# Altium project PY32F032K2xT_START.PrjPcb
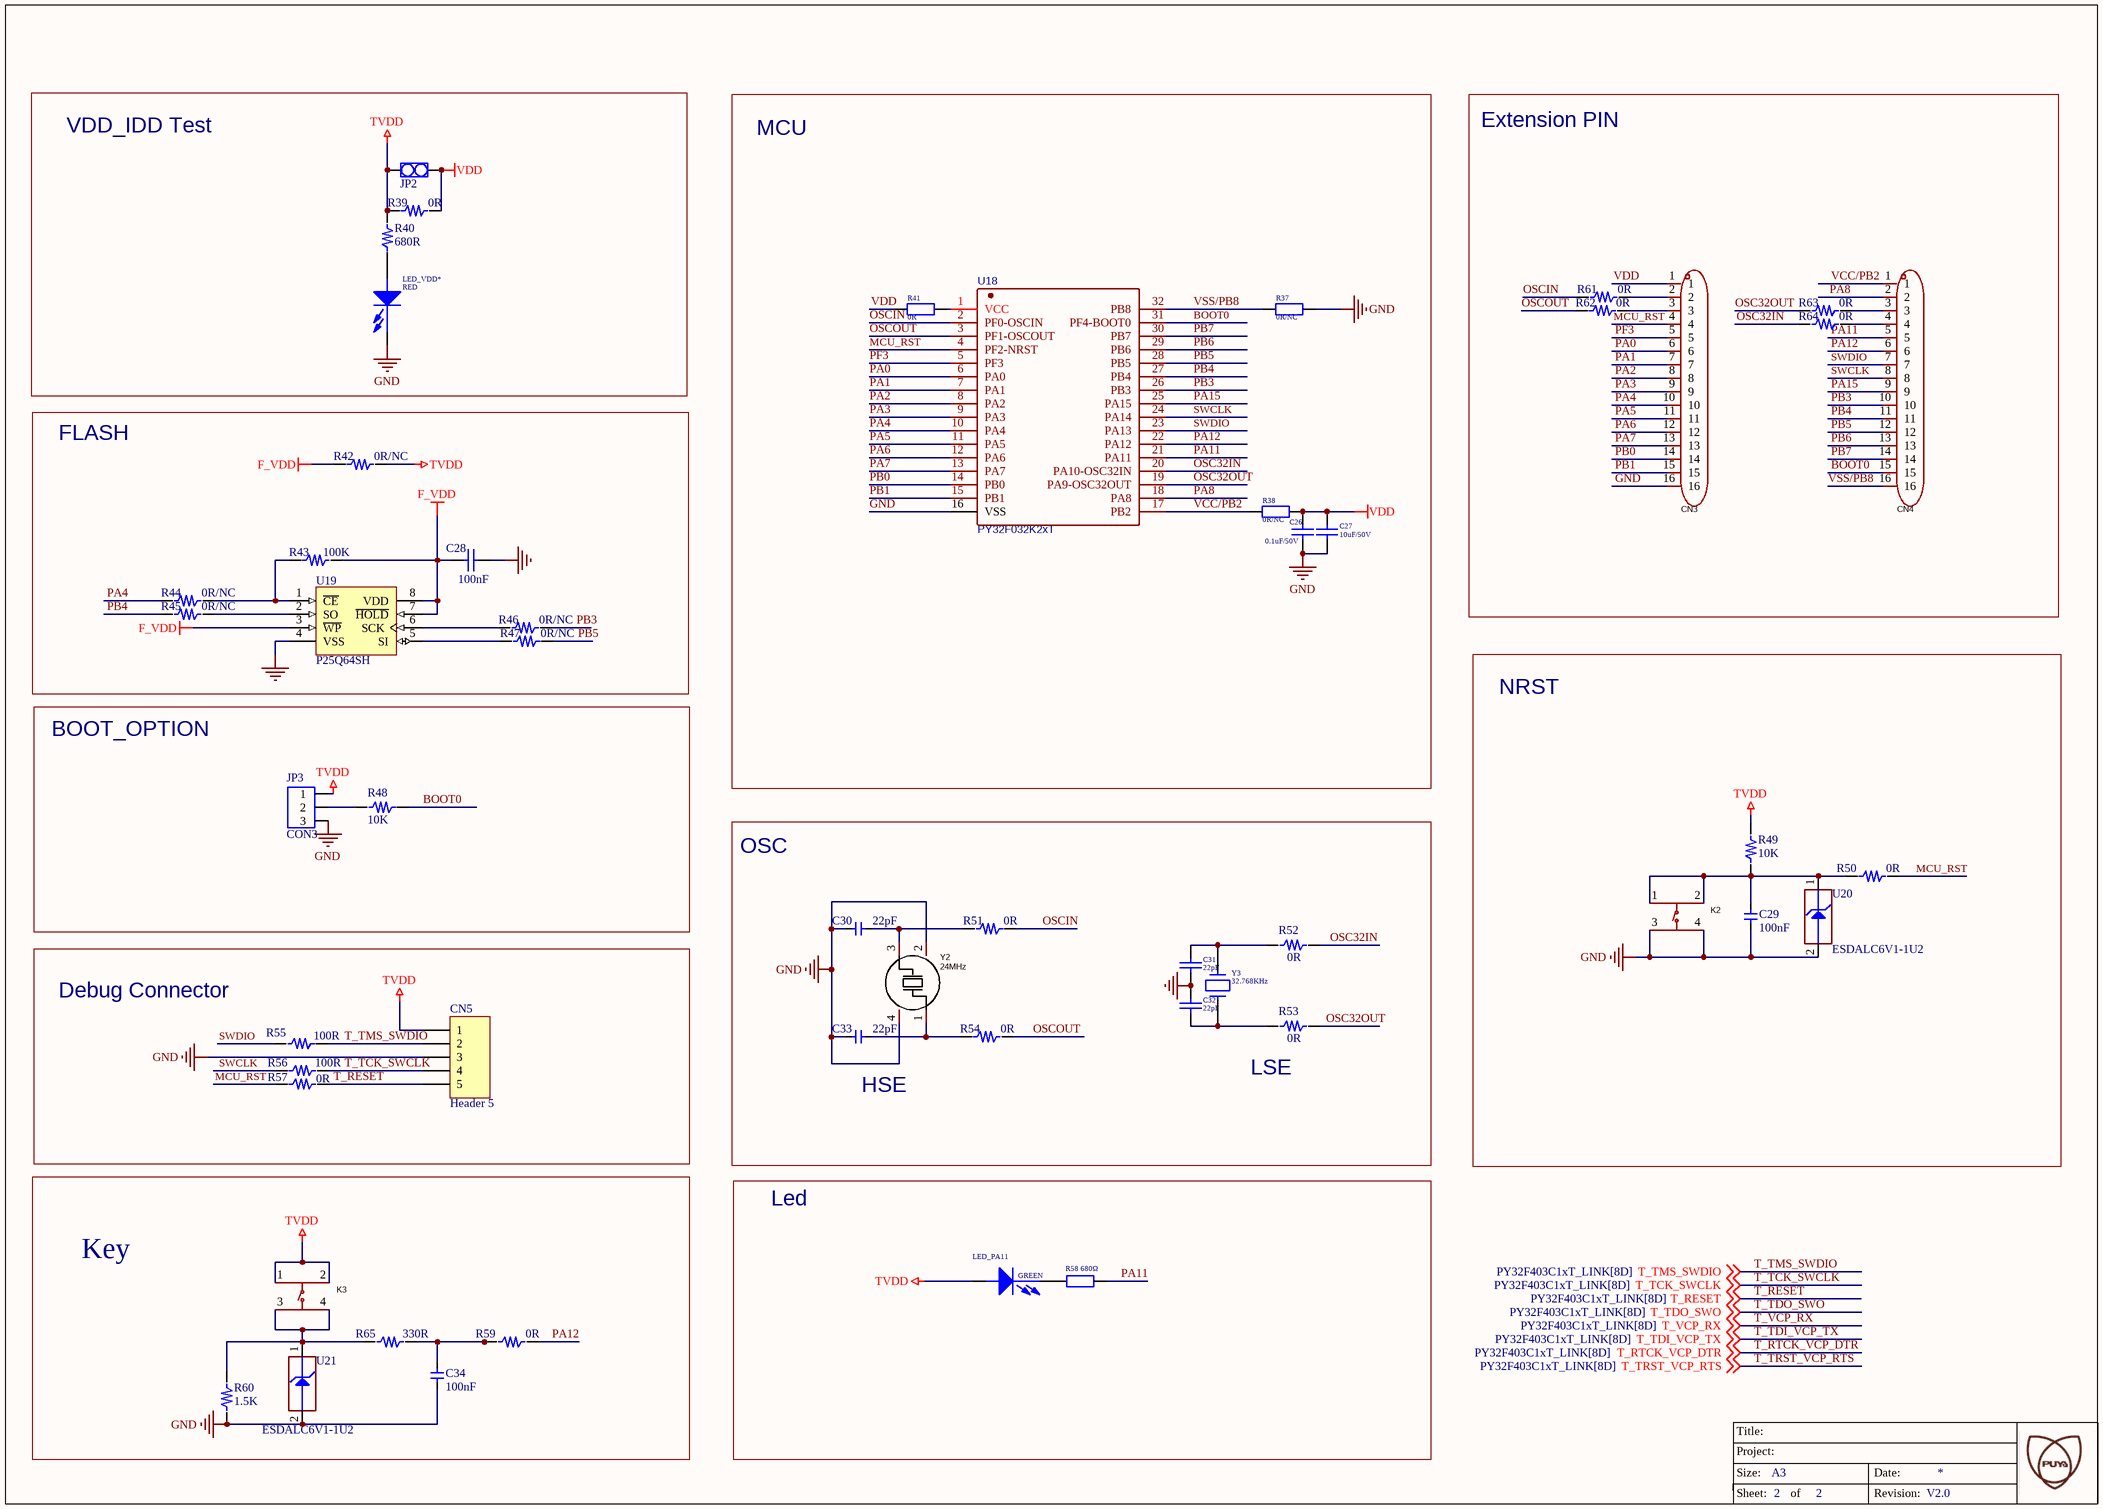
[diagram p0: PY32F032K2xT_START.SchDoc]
2 sheets, 141 parts. Net scope: global (net labels, ports and power ports of the same name join across sheets).
Board file: PY32F032K2xT_START.PcbDoc
Sheets:
  PY32F032K2xT_START.SchDoc
  PY32F403C1xT_LINK.SchDoc

## Sheet PY32F032K2xT_START.SchDoc: =DocumentName
size A3; Revision: V2.0; SheetNumber: 2; SheetTotal: 2; Project: PY32F032K2xT_START.PrjPcb

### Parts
C26  0.1uF/50V  [0603C]
C27  10uF/50V  [0603C]
C28  100nF  [C0603]
C29  100nF  [C0603]
C30  22pF  [C0603]
C31  22pF  [0603C]
C32  22pF  [0603C]
C33  22pF  [C0603]
C34  100nF  [C0603]
CN3  X6511WV-18H-C60D30  [CON 1X16P]  (value not drawn)
CN4  X6511WV-18H-C60D30  [CON 1X16P]  (value not drawn)
CN5  Header 5  [HDR1X5]
JP2  CON2  [CON2]  (value not drawn)
JP3  CON3  [CON3]
K2  TS-KG02S  [SWITCH]  (value not drawn)
K3  TS-KG02S  [SWITCH]  (value not drawn)
LED_PA11  GREEN  [0603_LED]
LED_VDD*  RED  [0603_LED]
R37  0R/NC  [R0603]
R38  0R/NC  [R0603]
R39  0R  [JP2_SMD]
R40  680R  [R0603]
R41  0R  [R0603]
R42  0R/NC  [JP2_SMD]
R43  100K  [R0603]
R44  0R/NC  [JP2_SMD]
R45  0R/NC  [JP2_SMD]
R46  0R/NC  [JP2_SMD]
R47  0R/NC  [JP2_SMD]
R48  10K  [R0603]
R49  10K  [R0603]
R50  0R  [JP2_SMD]
R51  0R  [JP2_SMD]
R52  0R  [JP2_SMD]
R53  0R  [JP2_SMD]
R54  0R  [JP2_SMD]
R55  100R  [R0603]
R56  100R  [R0603]
R57  0R  [JP2_SMD]
R58  680Ω  [R0603]
R59  0R  [JP2_SMD]
R60  1.5K  [R0603]
R61  0R  [JP2_SMD]
R62  0R  [JP2_SMD]
R63  0R  [JP2_SMD]
R64  0R  [JP2_SMD]
R65  330R  [R0603]
U18  PY32F032K2xT  [LQFP-32_L7.0-W7.0-P0.80-LS9.0-BL]
U19  P25Q64SH  [SOP-8P]
U20  value ESDALC6V1-1U2  [ESD_ST0201]  (hidden comment: ESD-TRANSIL)
U21  value ESDALC6V1-1U2  [ESD_ST0201]  (hidden comment: ESD-TRANSIL)
Y2  24MHz  [CRYSTAL-SMD_4P-L3.2-W2.5-BL]
Y3  32.768KHz  [CRYSTAL-SMD_L3.2-W1.5-1]

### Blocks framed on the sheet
VDD_IDD Test: JP2 LED_VDD* R39 R40
MCU: C26 C27 R37 R38 R41 U18
Extension PIN: CN3 CN4 R61-R64
FLASH: C28 R42-R47 U19
NRST: C29 K2 R49 R50 U20
BOOT_OPTION: JP3 R48
Debug Connector: CN5 R55-R57
Key: C34 K3 R59 R60 R65 U21
Led: LED_PA11 R58

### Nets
F_VDD: C28.2 R42.1 R43.2 U19.3(~{WP}) U19.7(~{HOLD}) U19.8(VDD)
GND: C26.1 C27.1 C28.1 C29.1 C30.1 C31.2 C32.1 C33.1 C34.1 CN3.16 CN5.3 JP3.3 K2.3 K2.4 LED_VDD*.2(CATHODE) R37.2 R60.1 U18.16(VSS) U19.4(VSS) U20.2(GND) U21.2(GND) Y2.2(GND) Y2.4(GND)
TVDD: CN5.1 JP2.1 JP3.1 K3.1 K3.2 LED_PA11.1(ANODE) R39.1 R40.2 R42.2 R49.1
VDD: C26.2 C27.2 CN3.1 JP2.2 R38.2 R39.2 R41.1
BOOT0: CN4.15 R48.2 U18.31(PF4-BOOT0)
MCU_RST: CN3.4 R50.2 R57.2 U18.4(PF2-NRST)
OSC32IN: R52.1 R64.1 U18.20(PA10-OSC32IN)
OSC32OUT: R53.1 R63.1 U18.19(PA9-OSC32OUT)
OSCIN: R51.2 R61.1 U18.2(PF0-OSCIN)
OSCOUT: R54.2 R62.1 U18.3(PF1-OSCOUT)
PA0: CN3.6 U18.6(PA0)
PA1: CN3.7 U18.7(PA1)
PA2: CN3.8 U18.8(PA2)
PA3: CN3.9 U18.9(PA3)
PA4: CN3.10 R44.1 U18.10(PA4)
PA5: CN3.11 U18.11(PA5)
PA6: CN3.12 U18.12(PA6)
PA7: CN3.13 U18.13(PA7)
PA8: CN4.2 U18.18(PA8)
PA11: CN4.5 R58.2 U18.21(PA11)
PA12: CN4.6 R59.2 U18.22(PA12)
PA15: CN4.9 U18.25(PA15)
PB0: CN3.14 U18.14(PB0)
PB1: CN3.15 U18.15(PB1)
PB3: CN4.10 R46.2 U18.26(PB3)
PB4: CN4.11 R45.1 U18.27(PB4)
PB5: CN4.12 R47.2 U18.28(PB5)
PB6: CN4.13 U18.29(PB6)
PB7: CN4.14 U18.30(PB7)
PF3: CN3.5 U18.5(PF3)
SWCLK: CN4.8 R56.2 U18.24(PA14)
SWDIO: CN4.7 R55.2 U18.23(PA13)
T_RESET: CN5.5 R57.1 ; off-sheet T_RESET
T_TCK_SWCLK: CN5.4 R56.1 ; off-sheet T_TCK_SWCLK
T_TMS_SWDIO: CN5.2 R55.1 ; off-sheet T_TMS_SWDIO
VCC/PB2: CN4.1 R38.1 U18.17(PB2)
VSS/PB8: CN4.16 R37.1 U18.32(PB8)
NetC29_2: C29.2 K2.1 K2.2 R49.2 R50.1 U20.1(IO1)
NetC30_2: C30.2 R51.1 Y2.3(OSC2)
NetC31_1: C31.1 R52.2 Y3.2
NetC32_2: C32.2 R53.2 Y3.1
NetC33_2: C33.2 R54.1 Y2.1(OSC1)
NetC34_2: C34.2 R59.1 R65.1
NetCN3_2: CN3.2 R61.2
NetCN3_3: CN3.3 R62.2
NetCN4_3: CN4.3 R63.2
NetCN4_4: CN4.4 R64.2
NetJP3_2: JP3.2 R48.1
NetK3_3: K3.3 K3.4 R60.2 R65.2 U21.1(IO1)
NetLED_PA11_2: LED_PA11.2(CATHODE) R58.1
NetLED_VDD*_1: LED_VDD*.1(ANODE) R40.1
NetR41_2: R41.2 U18.1(VCC)
NetR43_1: R43.1 R44.2 U19.1(~{CE})
NetR45_2: R45.2 U19.2(SO)
NetR46_1: R46.1 U19.6(SCK)
NetR47_1: R47.1 U19.5(SI)

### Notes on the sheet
- OSC
- (near C33) HSE
- (near R53) LSE

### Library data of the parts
C26 C27 = CAP: Capacitor; Value: 2.2uF
C28 = 贴片高压陶瓷电容: Capacitor (Semiconductor SIM Model); 器件封装(外观): 0603; Value: 104
C29 C30 C33 C34 = C0603: PCB DECAL: 0603
C31 C32 = Cap: Capacitor
CN3 CN4 = CON 1X16P: Manufacturer: XKB Connection(中国星坤); Symbol: X6511WV-18H-C30D60; Add into BOM: yes; Pin Structure: 1x18P; Pitch: 2.54mm; Circluar Pins/Square Pins: 方针; Current Rating (Max): 3A; Voltage Rating (Max): 250V; Soldering Temperature(Max): 260℃
CN5 = Header 5: Header, 5-Pin
JP2 = CON2_DIP
K2 K3 = TS-KG02S-AT50F: Manufacturer: HANBO(汉博); Add into BOM: yes; Circuit: 单刀单掷; Actuator Style: 圆形按钮; Operating Force: 250gf; Switch Length: 6mm; Switch Height: 5mm; Strike Gundam: 不带; Contact Current: 50mA; Voltage Rating (DC): 12V; Insulation Resistance: 100MΩ; Actuator/Cap Color: 黑色; Pin Style: 鸥翼型
LED_PA11 LED_VDD* = PDI-E803_Dup1
R37 R38 R41 R58 = Res: Resistor; 器件封装(外观): 0603; Value: 10K
R39 R40 R42-R57 R59-R65 = R0603: PCB DECAL: 0603
U18 = PY32F032K2xT: LQFP32(7*7); BOM_Manufacturer: PUYA(普冉)
U19 = SST25VF010: Value: SST25VF020B; 器件封装(外观): SOP8
U20 U21 = ESD-TRANSIL: ESD protection 6V1; Internal_Part_Number: MCD-00170; Part_Type: Diode; Manufacturer: STMICROELECTRONICS; ECCN_US: EAR99; ECCN_EU: NEC; Provided_By: Subcon; Initial_Board_Reference: MB1274
Y2 = ABM8AIG-24.000MHZ-82Z-T: ±20ppm , 12.5pF , T_use: -40°C~125°C; Manufacturer: ABRACON; Add into BOM: yes; External load capacitor: 8pF; Frequency Stability(Full temperature range): ±50ppm; Equivalent Series Resistance (ESR): 50Ω
Y3 = CRYSTAL_1: Crystal; Value: X503225MSB2GI

## Sheet PY32F403C1xT_LINK.SchDoc: =DocumentName
size A3; Revision: V2.0; SheetNumber: 1; SheetTotal: 2; Project: PY32F032K2xT_START.PrjPcb
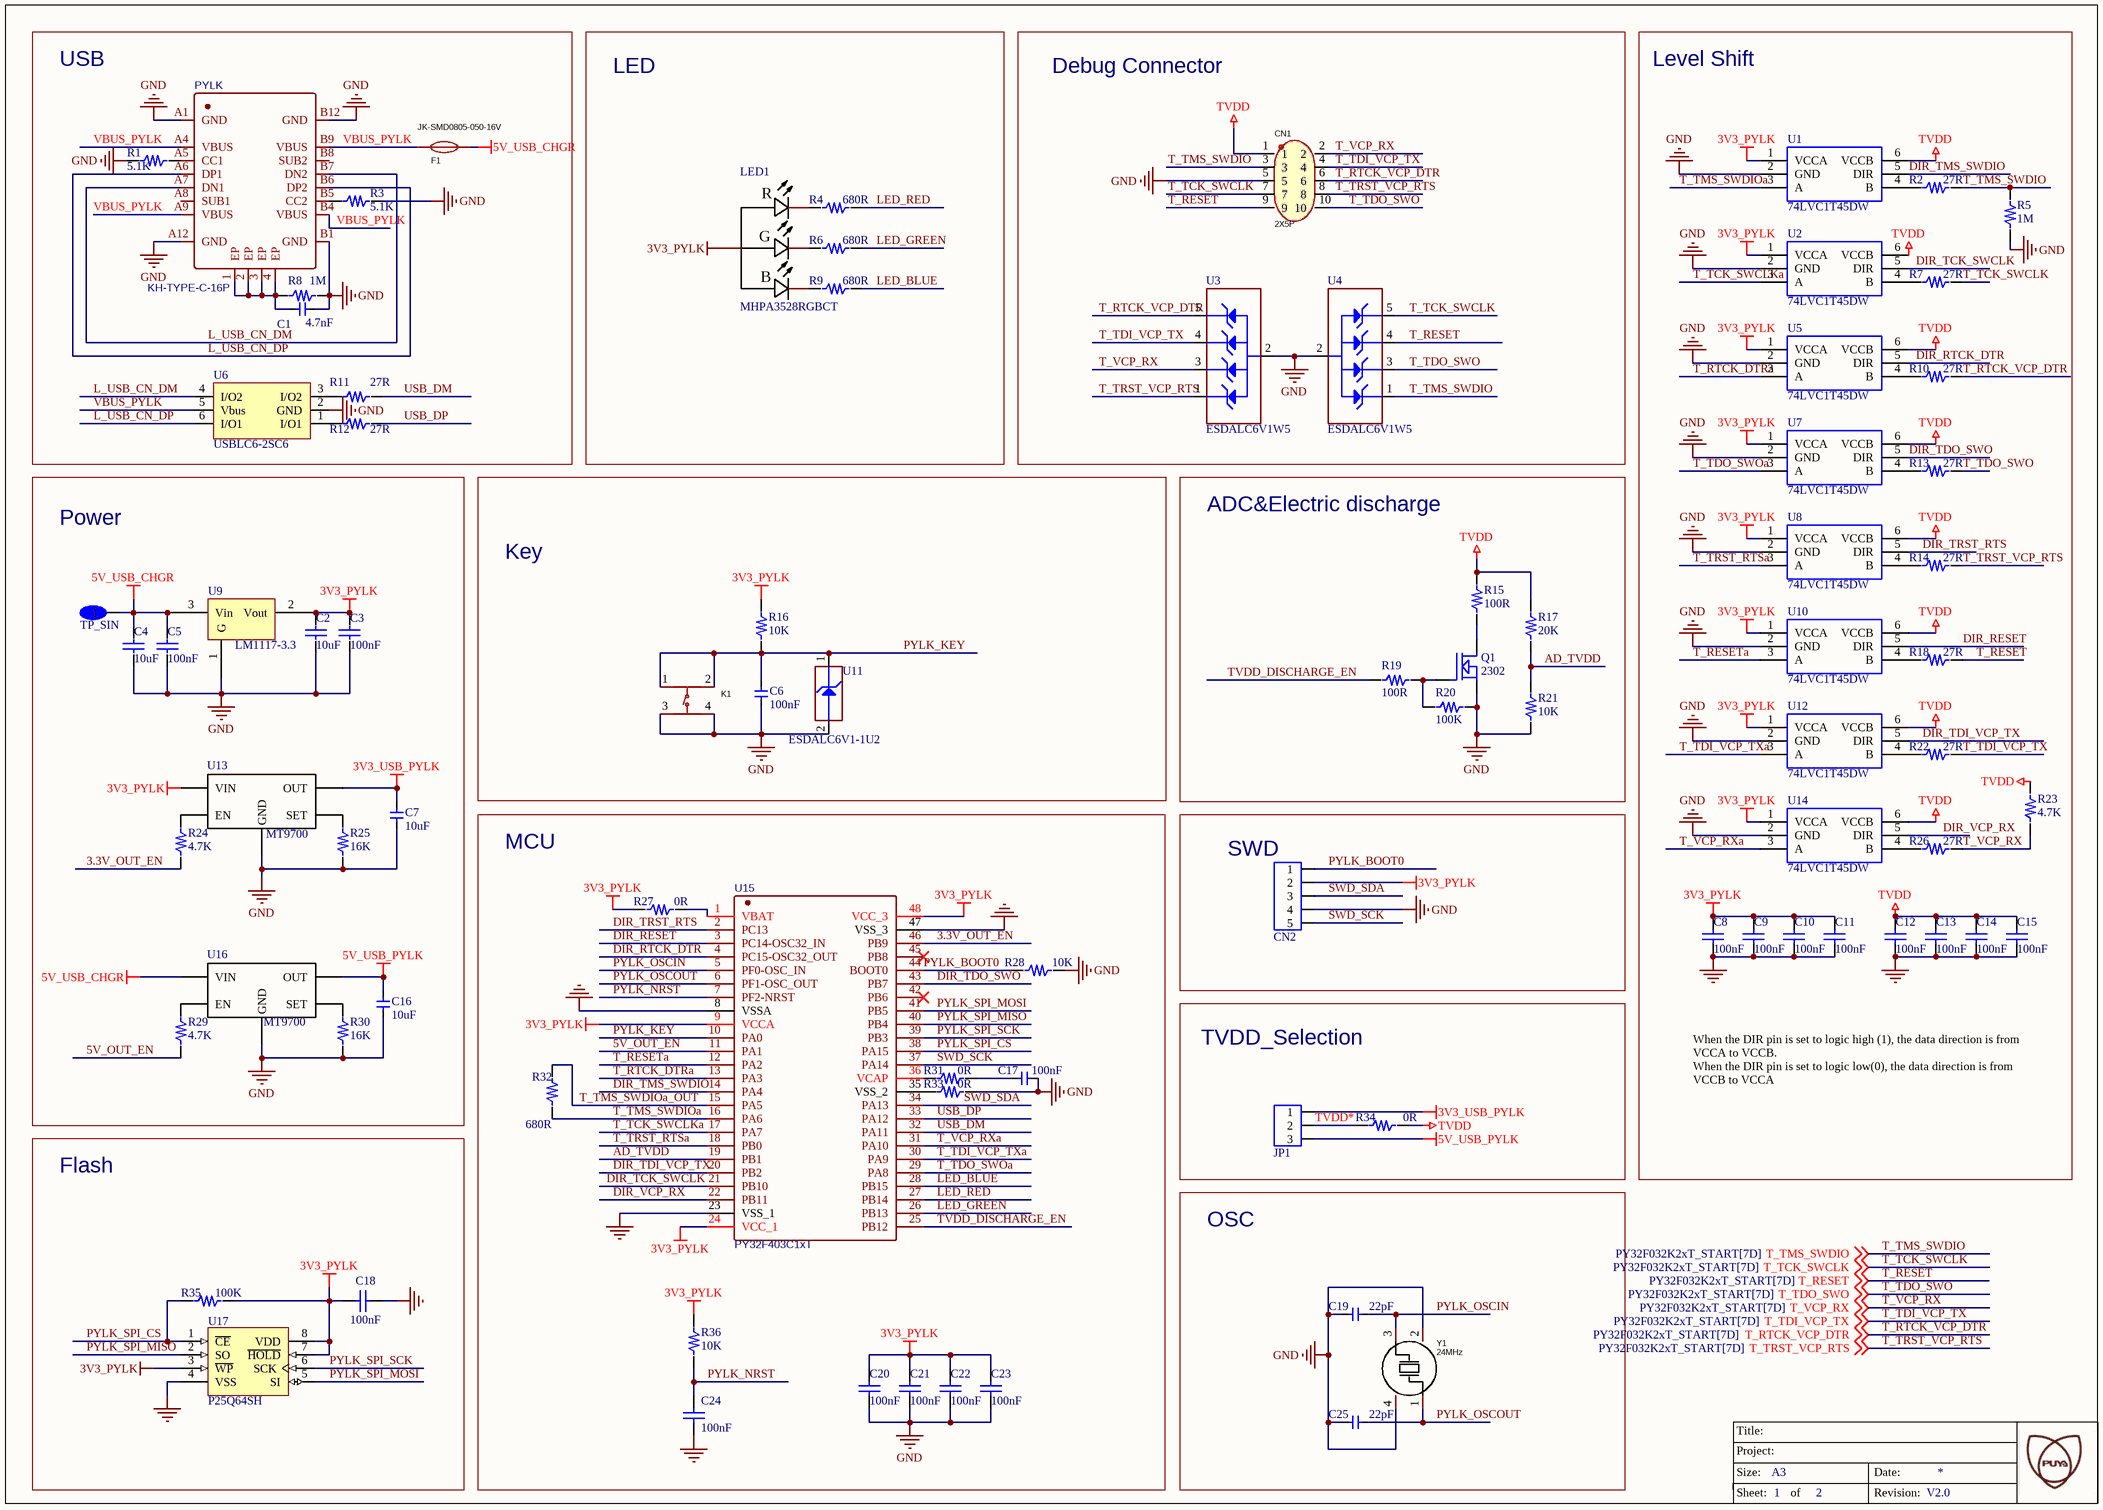
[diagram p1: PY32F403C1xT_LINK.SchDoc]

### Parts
5V_USB_CHGR  TP_SIN  [TP_SIN]
C1  4.7nF  [C0603]
C2  10uF  [C0805]
C3  100nF  [C0603]
C4  10uF  [C0805]
C5  100nF  [C0603]
C6  100nF  [C0603]
C7  10uF  [C0805]
C8  100nF  [C0603]
C9  100nF  [C0603]
C10  100nF  [C0603]
C11  100nF  [C0603]
C12  100nF  [C0603]
C13  100nF  [C0603]
C14  100nF  [C0603]
C15  100nF  [C0603]
C16  10uF  [C0805]
C17  100nF  [C0603]
C18  100nF  [C0603]
C19  22pF  [C0603]
C20  100nF  [C0603]
C21  100nF  [C0603]
C22  100nF  [C0603]
C23  100nF  [C0603]
C24  100nF  [C0603]
C25  22pF  [C0603]
CN1  2X5P  [HDR2X5]
CN2  CON5  [CON5]  (value not drawn)
F1  JK-SMD0805-050-16V  [F0805]
JP1  CON3  [CON3]  (value not drawn)
K1  TS-KG02S  [SWITCH]  (value not drawn)
LED1  MHPA3528RGBCT  [LED-ARRAY-SMD_4P-L3.5-W2.8-TL]
PYLK  KH-TYPE-C-16P  [USB-C-SMD_KH-TYPE-C-16P]
Q1  2302  [SOT23]
R1  5.1K  [R0603]
R2  27R  [R0603]
R3  5.1K  [R0603]
R4  680R  [R0603]
R5  1M  [R0603]
R6  680R  [R0603]
R7  27R  [R0603]
R8  1M  [R0603]
R9  680R  [R0603]
R10  27R  [R0603]
R11  27R  [R0603]
R12  27R  [R0603]
R13  27R  [R0603]
R14  27R  [R0603]
R15  100R  [R0805]
R16  10K  [R0603]
R17  20K  [R0603]
R18  27R  [R0603]
R19  100R  [R0603]
R20  100K  [R0603]
R21  10K  [R0603]
R22  27R  [R0603]
R23  4.7K  [R0603]
R24  4.7K  [R0603]
R25  16K  [R0603]
R26  27R  [R0603]
R27  0R  [JP2_SMD]
R28  10K  [R0603]
R29  4.7K  [R0603]
R30  16K  [R0603]
R31  0R  [JP2_SMD]
R32  680R  [R0603]
R33  0R  [JP2_SMD]
R34  0R  [JP2_SMD]
R35  100K  [R0603]
R36  10K  [R0603]
U1  74LVC1T45DW  [SOT363]
U2  74LVC1T45DW  [SOT363]
U3  value ESDALC6V1W5  [ESD_SOT323-5L]  (hidden comment: ESD_6V1)
U4  value ESDALC6V1W5  [ESD_SOT323-5L]  (hidden comment: ESD_6V1)
U5  74LVC1T45DW  [SOT363]
U6  USBLC6-2SC6  [SOT23-6]
U7  74LVC1T45DW  [SOT363]
U8  74LVC1T45DW  [SOT363]
U9  LM1117-3.3  [LM1117-3.3]
U10  74LVC1T45DW  [SOT363]
U11  value ESDALC6V1-1U2  [ESD_ST0201]  (hidden comment: ESD-TRANSIL)
U12  74LVC1T45DW  [SOT363]
U13  MT9700  [SOT23-5]
U14  74LVC1T45DW  [SOT363]
U15  PY32F403C1xT  [LQFP-48_L7.0-W7.0-P0.50-LS9.0-BL]
U16  MT9700  [SOT23-5]
U17  P25Q64SH  [SOP-8P]
Y1  24MHz  [CRYSTAL-SMD_4P-L3.2-W2.5-BL]

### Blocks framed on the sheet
USB: C1 F1 PYLK R1 R3 R8 R11 R12 U6
LED: LED1 R4 R6 R9
Debug Connector: CN1 U3 U4
Level Shift: C8-C15 R2 R5 R7 R10 R13 R14 R18 R22 R23 R26 U1 U2 U5 U7 U8 U10 U12 U14
Power: 5V_USB_CHGR C2-C5 C7 C16 R24 R25 R29 R30 U9 U13 U16
Key: C6 K1 R16 U11
ADC&Electric discharge: Q1 R15 R17 R19-R21
MCU: C17 C20-C24 R27 R28 R31-R33 R36 U15
SWD: CN2
TVDD_Selection: JP1 R34
Flash: C18 R35 U17
OSC: C19 C25 Y1

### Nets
3V3_PYLK: C2.2 C3.2 C8.2 C9.2 C10.2 C11.2 C18.2 C20.2 C21.2 C22.2 C23.2 CN2.2 LED1.1(-) R16.2 R27.1 R35.2 R36.2 U1.1(VCCA) U2.1(VCCA) U5.1(VCCA) U7.1(VCCA) U8.1(VCCA) U9.2(Vout) U10.1(VCCA) U12.1(VCCA) U13.5(VIN) U14.1(VCCA) U15.9(VCCA) U15.24(VCC_1) U15.48(VCC_3) U17.3(~{WP}) U17.7(~{HOLD}) U17.8(VDD)
3V3_USB_PYLK: C7.2 JP1.1 U13.1(OUT)
5V_USB_CHGR: 5V_USB_CHGR.1 C4.2 C5.2 F1.2 U9.3(Vin) U16.5(VIN)
5V_USB_PYLK: C16.2 JP1.3 U16.1(OUT)
GND: C1.1 C2.1 C3.1 C4.1 C5.1 C6.1 C7.1 C8.1 C9.1 C10.1 C11.1 C12.1 C13.1 C14.1 C15.1 C16.1 C17.1 C18.1 C19.1 C20.1 C21.1 C22.1 C23.1 C24.1 C25.1 CN1.5 CN2.4 K1.3 K1.4 PYLK.A1(GND) PYLK.A12(GND) PYLK.B1(GND) PYLK.B12(GND) Q1.2(S) R1.1 R3.2 R5.1 R8.2 R20.1 R21.1 R25.1 R28.2 R30.1 R33.2 U1.2(GND) U2.2(GND) U3.2(GND) U4.2(GND) U5.2(GND) U6.2(GND) U7.2(GND) U8.2(GND) U9.1(G) U10.2(GND) U11.2(GND) U12.2(GND) U13.2(GND) U14.2(GND) U15.8(VSSA) U15.23(VSS_1) U15.47(VSS_3) U16.2(GND) U17.4(VSS) Y1.2(GND) Y1.4(GND)
TVDD: C12.2 C13.2 C14.2 C15.2 CN1.1 R15.2 R17.2 R23.2 R34.2 U1.6(VCCB) U2.6(VCCB) U5.6(VCCB) U7.6(VCCB) U8.6(VCCB) U10.6(VCCB) U12.6(VCCB) U14.6(VCCB)
3.3V_OUT_EN: R24.1 U15.46(PB9)
5V_OUT_EN: R29.1 U15.11(PA1)
AD_TVDD: R17.1 R21.2 U15.19(PB1)
DIR_RESET: U10.5(DIR) U15.3(PC14-OSC32_IN)
DIR_RTCK_DTR: U5.5(DIR) U15.4(PC15-OSC32_OUT)
DIR_TCK_SWCLK: U2.5(DIR) U15.21(PB10)
DIR_TDI_VCP_TX: U12.5(DIR) U15.20(PB2)
DIR_TDO_SWO: U7.5(DIR) U15.43(PB7)
DIR_TMS_SWDIO: U1.5(DIR) U15.14(PA4)
DIR_TRST_RTS: U8.5(DIR) U15.2(PC13)
DIR_VCP_RX: U14.5(DIR) U15.22(PB11)
L_USB_CN_DM: PYLK.A7(DN1) PYLK.B7(DN2) U6.4(I/O2)
L_USB_CN_DP: PYLK.A6(DP1) PYLK.B6(DP2) U6.6(I/O1)
LED_BLUE: R9.2 U15.28(PB15)
LED_GREEN: R6.2 U15.26(PB13)
LED_RED: R4.2 U15.27(PB14)
PYLK_BOOT0: CN2.1 R28.1 U15.44(BOOT0)
PYLK_KEY: C6.2 K1.1 K1.2 R16.1 U11.1(IO1) U15.10(PA0)
PYLK_NRST: C24.2 R36.1 U15.7(PF2-NRST)
PYLK_OSCIN: C19.2 U15.5(PF0-OSC_IN) Y1.3(OSC2)
PYLK_OSCOUT: C25.2 U15.6(PF1-OSC_OUT) Y1.1(OSC1)
PYLK_SPI_CS: R35.1 U15.38(PA15) U17.1(~{CE})
PYLK_SPI_MISO: U15.40(PB4) U17.2(SO)
PYLK_SPI_MOSI: U15.41(PB5) U17.5(SI)
PYLK_SPI_SCK: U15.39(PB3) U17.6(SCK)
SWD_SCK: CN2.5 U15.37(PA14)
SWD_SDA: CN2.3 U15.34(PA13)
T_RESET: CN1.9 R18.2 U4.4(IO3) ; off-sheet T_RESET
T_RESETa: U10.3(A) U15.12(PA2)
T_RTCK_DTRa: U5.3(A) U15.13(PA3)
T_RTCK_VCP_DTR: CN1.6 R10.2 U3.5(IO4) ; off-sheet T_RTCK_VCP_DTR
T_TCK_SWCLK: CN1.7 R7.2 U4.5(IO4) ; off-sheet T_TCK_SWCLK
T_TCK_SWCLKa: U2.3(A) U15.17(PA7)
T_TDI_VCP_TX: CN1.4 R22.2 U3.4(IO3) ; off-sheet T_TDI_VCP_TX
T_TDI_VCP_TXa: U12.3(A) U15.30(PA9)
T_TDO_SWO: CN1.10 R13.2 U4.3(IO2) ; off-sheet T_TDO_SWO
T_TDO_SWOa: U7.3(A) U15.29(PA8)
T_TMS_SWDIO: CN1.3 R2.2 R5.2 U4.1(IO1) ; off-sheet T_TMS_SWDIO
T_TMS_SWDIOa: R32.1 U1.3(A) U15.16(PA6)
T_TMS_SWDIOa_OUT: R32.2 U15.15(PA5)
T_TRST_RTSa: U8.3(A) U15.18(PB0)
T_TRST_VCP_RTS: CN1.8 R14.2 U3.1(IO1) ; off-sheet T_TRST_VCP_RTS
T_VCP_RX: CN1.2 R23.1 R26.2 U3.3(IO2) ; off-sheet T_VCP_RX
T_VCP_RXa: U14.3(A) U15.31(PA10)
TVDD*: JP1.2 R34.1
TVDD_DISCHARGE_EN: R19.2 U15.25(PB12)
USB_DM: R11.2 U15.32(PA11)
USB_DP: R12.2 U15.33(PA12)
VBUS_PYLK: F1.1 PYLK.A4(VBUS) PYLK.A9(VBUS) PYLK.B4(VBUS) PYLK.B9(VBUS) U6.5(Vbus)
NetC1_2: C1.2 PYLK.1(EP) PYLK.2(EP) PYLK.3(EP) PYLK.4(EP) R8.1
NetC17_2: C17.2 R31.2
NetLED1_2: LED1.2(-) R9.1
NetLED1_3: LED1.3(-) R6.1
NetLED1_4: LED1.4(-) R4.1
NetPYLK_A5: PYLK.A5(CC1) R1.2
NetPYLK_B5: PYLK.B5(CC2) R3.1
NetQ1_1: Q1.1(G) R19.1 R20.2
NetQ1_3: Q1.3(D) R15.1
NetR2_1: R2.1 U1.4(B)
NetR7_1: R7.1 U2.4(B)
NetR10_1: R10.1 U5.4(B)
NetR11_1: R11.1 U6.3(I/O2)
NetR12_1: R12.1 U6.1(I/O1)
NetR13_1: R13.1 U7.4(B)
NetR14_1: R14.1 U8.4(B)
NetR18_1: R18.1 U10.4(B)
NetR22_1: R22.1 U12.4(B)
NetR24_2: R24.2 U13.4(EN)
NetR25_2: R25.2 U13.3(SET)
NetR26_1: R26.1 U14.4(B)
NetR27_2: R27.2 U15.1(VBAT)
NetR29_2: R29.2 U16.4(EN)
NetR30_2: R30.2 U16.3(SET)
NetR31_1: R31.1 U15.36(VCAP)
NetR33_1: R33.1 U15.35(VSS_2)

Not connected (* = marked no-connect by the designer): PYLK A8(SUB1) B8(SUB2); U15 42(PB6)* 45(PB8)*

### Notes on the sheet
- When the DIR pin is set to logic high (1), the data direction is from VCCA to VCCB.
  When the DIR pin is set to logic low(0), the data direction is from VCCB to VCCA

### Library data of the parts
C1 C3 C5 C6 C17 C19 C25 = C0603: PCB DECAL: 0603
C2 C4 C7 C16 = C0805: PCB DECAL: 0805
C8-C15 C18 C20-C24 = 贴片高压陶瓷电容: as C28 on sheet PY32F032K2xT_START
CN1 = 2X5P: Manufacturer: XFCN(兴飞); Symbol: PZ254V-12-10P; Add into BOM: yes; Pitch: 2.54mm; Circluar Pins/Square Pins: 方针
F1 = JK-SMD0805-050-16V: Manufacturer: JK(金科); Add into BOM: yes; Voltage - Max: 6V; Current - Max: 100A; Hold Current: 500mA; Trip Current: 1A; Power Dissipation: 600mW; Resistance - Initial (Ri) (Min): 150mΩ; Resistance - Post Trip (R1) (Max): 850mΩ; Time to Trip(Max): 100ms
K1 = TS-KG02S-AT50F: as K2 on sheet PY32F032K2xT_START
LED1 = MHPA3528RGBCT: Manufacturer: MEIHUA(美华); Add into BOM: yes
PYLK = KH-TYPE-C-16P: BOM_Manufacturer: Shenzhen Kinghelm Elec; Contributor: LCSC
Q1 = MOSFET N: Value: SI2302
R1-R14 R16-R36 = R0603: PCB DECAL: 0603
R15 = R0805: PCB DECAL: 0805
U3 U4 = ESDALC6V1W5: Dual Transil array for ESD protection; Internal_Part_Number: MCD-00136; Part_Type: Diode; Manufacturer: STMICROELECTRONICS; ECCN_US: EAR99; ECCN_EU: NEC; Provided_By: Subcon; Initial_Board_Reference: MB1262
U6 = USBLC6-2SC6: Function: ESD EMI fliter
U11 = ESD-TRANSIL: as U20 on sheet PY32F032K2xT_START
U15 = PY32F403C1xT: LQFP48; BOM_Manufacturer: PUYA(普冉)
U17 = SST25VF010: Value: SST25VF020B; 器件封装(外观): SOP8
Y1 = ABM8AIG-24.000MHZ-82Z-T: as Y2 on sheet PY32F032K2xT_START

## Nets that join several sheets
GND: PY32F032K2xT_START (23 pins), PY32F403C1xT_LINK (65 pins)
TVDD: PY32F032K2xT_START (10 pins), PY32F403C1xT_LINK (17 pins)
T_RESET: PY32F032K2xT_START (CN5.5 R57.1), PY32F403C1xT_LINK (CN1.9 R18.2 U4.4)
T_TCK_SWCLK: PY32F032K2xT_START (CN5.4 R56.1), PY32F403C1xT_LINK (CN1.7 R7.2 U4.5)
T_TMS_SWDIO: PY32F032K2xT_START (CN5.2 R55.1), PY32F403C1xT_LINK (CN1.3 R2.2 R5.2 U4.1)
